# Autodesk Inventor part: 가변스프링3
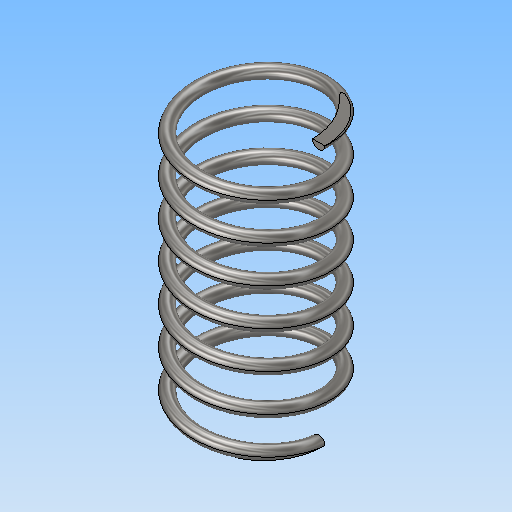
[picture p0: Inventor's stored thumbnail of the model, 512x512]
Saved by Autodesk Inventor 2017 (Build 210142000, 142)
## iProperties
Part Number: 가변스프링3
Material: 스테인레스 스틸
Document SubType Name: Modeling
Designer: MRC
Density: 8 g/cm^3
Appearance: 반연마
Mass: 10.9602 g
Surface Area: 27.6886 cm^2
Volume: 1.37003 cm^3
Author: MRC
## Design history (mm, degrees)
sketch "스케치1"
  geometry: L1 (0, 0)-(10, 0); L2 (10, 0)-(10, 41.411); L3 (10, 41.411)-(0, 41.411); L4 (0, 41.411)-(0, 0); C1 r 1 at (10, 0)
  constraints: 8 end point, 2 parallel, 1 centre point, 1 coincident, 1 horizontal, 1 perpendicular
  dimensions: "d1" = 41.4112 distance of L3.end L1.start (derived); "d2" = 20 diameter of L2 L4; "d3" = 2 diameter of C1
feature "코일1" sketch "스케치1" pitch "d4" = 10; turns "d6" = 7; dims "d5" = 41.4112 (= d1), "d7" = 0, angle "d8" = 90 deg, angle "d9" = 90 deg, "d10" = 0, "d11" = 0
sketch "스케치2"
  geometry: L1 (-20, 41.411)-(20, 41.411); L2 (20, 41.411)-(20, 0); L3 (20, 0)-(-20, 0); L4 (-20, 0)-(-20, 41.411); L5 (0, 41.411)-(0, 0) reference; 2 further points
  constraints: 8 end point, 2 midpoint, 2 parallel, 1 coincident, 1 horizontal, 1 perpendicular
  dimensions: "d12" = 40 distance between parallel lines of L4 L2
extrude "돌출1" sketch "스케치2" stored distance "d13" = 0; taper "d14" = 0 deg
node "솔리드1"
